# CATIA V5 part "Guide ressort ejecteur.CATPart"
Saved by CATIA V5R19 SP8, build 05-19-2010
Part number: Guide ressort ejecteur
Bounding box of the stored display mesh (mm): x -15 to 0, y -1.439 to 1.439, z -1.439 to 1.439
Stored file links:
  C:\Users\Arthur\Desktop\Catia parts\Guide ressort ejecteur.CATPart
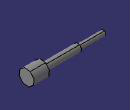
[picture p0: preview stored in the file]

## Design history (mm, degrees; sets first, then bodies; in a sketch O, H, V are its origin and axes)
Set1
  Sketch1 on zx-plane, origin (0, 0, 0), H (-1, 0, 0), V (0, 0, 1)
    axis line L1 (-10, 0) -> (80, 0)
    line L2 (0, 0) -> (0, 1.5)
    line L3 (0, 1.5) -> (3, 1.5)
    line L4 (3, 1.5) -> (3, 0.75)
    line L5 (3, 0.75) -> (10, 0.75)
    line L6 (10, 0.75) -> (10, 0.5)
    line L7 (10, 0.5) -> (15, 0.5)
    line L8 (15, 0.5) -> (15, 0)
    point P9 (15, 0)
    length L3 = 3
    length L7 = 5
    distance L8 L2 = 15
    distance L3 L1 = 1.5
    distance L5 L3 = 0.75
    distance L7 L5 = 0.25
    horizontal: L1 H, L3 H, L5 H, L7 H
    coincidence: L1 H, P9 L1
    vertical: L2 V, L4 V, L6 V, L8 V
Body1 (main body)
  Shaft1: profile Sketch1, axis Sketch1.L1, angle 360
